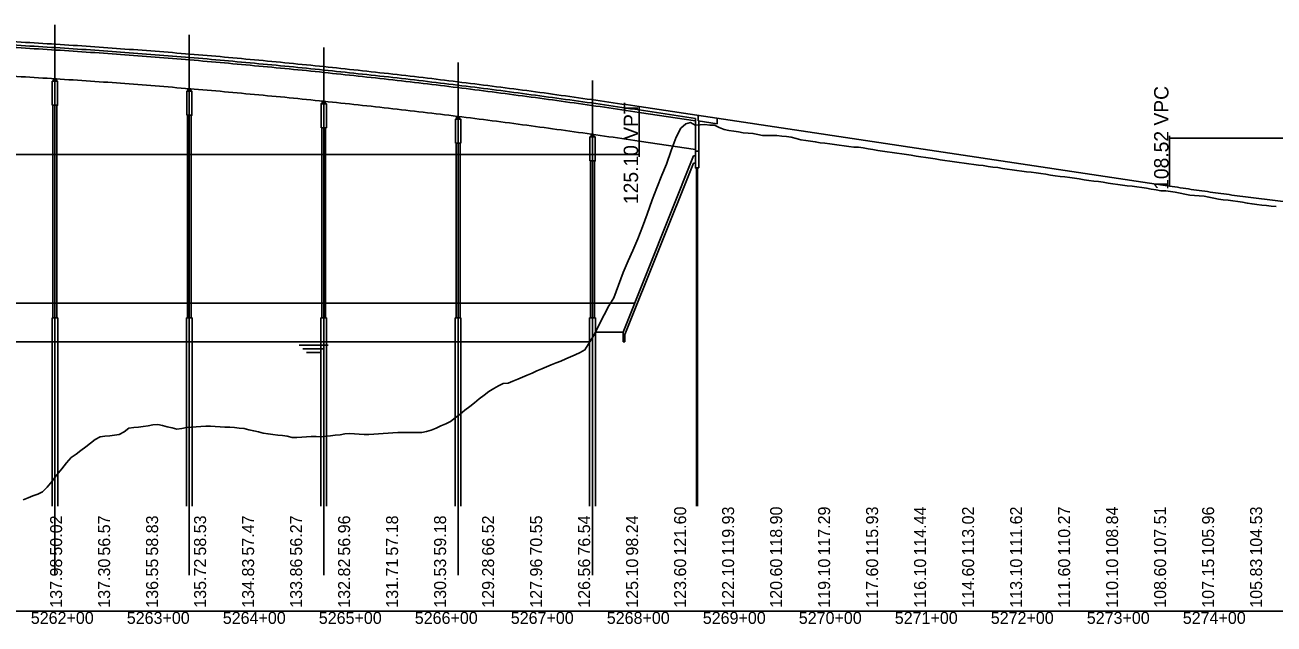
# Model space of a CAD drawing. Extents: x 2121671 to 2169879, y 557274 to 599957.
# Drawn here: x 2155728 to 2157029, y 579173 to 579797 of the extents above; entities that cross this region are included whole.
import ezdxf

# ---------------------------------------------------------------- set-up
doc = ezdxf.new("R2010")
doc.units = 0
for name, color, linetype in [('BR_CENTER LINES', 7, 'Continuous'), ('BR_CONCRETE', 7, 'Continuous'), ('BR_DETAILS', 7, 'Continuous'), ('BR_PRESTRESSED BEAM', 7, 'Continuous'), ('BR_STRUCTURAL STEEL', 7, 'Continuous'), ('RD_DDB_Profile_Elev', 7, 'Continuous'), ('RD_DDB_Profile_EX', 7, 'Continuous'), ('RD_DDB_Profile_PR', 7, 'Continuous'), ('RD_DDB_StaTX', 7, 'Continuous'), ('RD_DDB_StripGrade', 7, 'Continuous'), ('RD_DDB_VCLbl', 7, 'Continuous'), ('RD_GPK_Profile_Cell', 7, 'Continuous')]:
    doc.layers.add(name, color=color, linetype=linetype)

msp = doc.modelspace()

# ---------------------------------------------------------------- linework, layer by layer
at = {"layer": 'BR_CENTER LINES'}
for p, q in [((2155759.4, 579224.3), (2155759.4, 579797.3)), ((2155899.4, 579224.3), (2155899.4, 579787)), ((2156039.4, 579224.3), (2156039.4, 579773.9)), ((2156179.4, 579224.3), (2156179.4, 579758.1)), ((2156319.4, 579224.3), (2156319.4, 579739.4))]:
    msp.add_line(p, q, dxfattribs=at)
at = {"layer": 'BR_CONCRETE'}
for p, q in [((2155757.4, 579713.7), (2155757.4, 579492.4)), ((2155761.4, 579713.7), (2155761.4, 579492.4)), ((2155897.4, 579703.3), (2155897.4, 579492.4)), ((2155901.4, 579703.3), (2155901.4, 579492.4)), ((2156367.9, 579708.8), (2156426.6, 579700)), ((2156429.4, 579697.3), (2156429.4, 579703.1)), ((2156037.4, 579690.2), (2156037.4, 579492.4)), ((2156041.4, 579690.2), (2156041.4, 579492.4)), ((2156426.6, 579665.9), (2156426.6, 579700)), ((2156429.4, 579697.3), (2156449.4, 579694.3)), ((2156430.1, 579665.9), (2156430.1, 579697.2)), ((2156449.4, 579694.3), (2156449.4, 579700.1)), ((2156177.4, 579674.3), (2156177.4, 579492.4)), ((2156181.4, 579674.3), (2156181.4, 579492.4)), ((2156317.4, 579655.7), (2156317.4, 579492.4)), ((2156321.4, 579655.7), (2156321.4, 579492.4)), ((2155756.4, 579492.4), (2155756.4, 579296.1)), ((2155756.4, 579492.4), (2155762.4, 579492.4)), ((2155762.4, 579492.4), (2155762.4, 579296.1)), ((2155896.4, 579492.4), (2155896.4, 579296.1)), ((2155896.4, 579492.4), (2155902.4, 579492.4)), ((2155902.4, 579492.4), (2155902.4, 579296.1)), ((2156036.4, 579492.4), (2156036.4, 579296.1)), ((2156036.4, 579492.4), (2156042.4, 579492.4)), ((2156042.4, 579492.4), (2156042.4, 579296.1)), ((2156176.4, 579492.4), (2156176.4, 579296.1)), ((2156176.4, 579492.4), (2156182.4, 579492.4)), ((2156182.4, 579492.4), (2156182.4, 579296.1)), ((2156316.4, 579492.4), (2156316.4, 579296.1)), ((2156316.4, 579492.4), (2156322.4, 579492.4)), ((2156322.4, 579492.4), (2156322.4, 579296.1))]:
    msp.add_line(p, q, dxfattribs=at)
for points in [[(2155756.7, 579713.7), (2155762.2, 579713.7), (2155762.2, 579738.7), (2155756.7, 579738.7)], [(2155896.7, 579703.3), (2155902.2, 579703.3), (2155902.2, 579728.3), (2155896.7, 579728.3)], [(2156036.7, 579690.2), (2156042.2, 579690.2), (2156042.2, 579715.2), (2156036.7, 579715.2)], [(2156176.7, 579674.3), (2156182.2, 579674.3), (2156182.2, 579699.3), (2156176.7, 579699.3)], [(2156316.7, 579655.7), (2156322.2, 579655.7), (2156322.2, 579680.7), (2156316.7, 579680.7)], [(2156430.1, 579648.4), (2156426.6, 579648.4), (2156426.6, 579665.9), (2156430.1, 579665.9)]]:
    msp.add_lwpolyline(points, close=True, dxfattribs=at)
msp.add_spline([(2154567.9, 579748.7), (2154603.9, 579752.4), (2154639.9, 579755.9), (2154675.9, 579759.3), (2154711.9, 579762.4), (2154747.9, 579765.4), (2154783.9, 579768.2), (2154819.9, 579770.8), (2154855.9, 579773.2), (2154891.9, 579775.5), (2154927.9, 579777.5), (2154963.9, 579779.4), (2154999.9, 579781.1), (2155035.9, 579782.6), (2155071.9, 579783.9), (2155107.9, 579785), (2155143.9, 579786), (2155179.9, 579786.8), (2155215.9, 579787.3), (2155251.9, 579787.7), (2155287.9, 579787.9), (2155323.9, 579788), (2155359.9, 579787.8), (2155395.9, 579787.5), (2155431.9, 579787), (2155467.9, 579786.3), (2155503.9, 579785.4), (2155539.9, 579784.3), (2155575.9, 579783), (2155611.9, 579781.6), (2155647.9, 579780), (2155683.9, 579778.2), (2155719.9, 579776.2), (2155755.9, 579774), (2155791.9, 579771.6), (2155827.9, 579769.1), (2155863.9, 579766.3), (2155899.9, 579763.4), (2155935.9, 579760.3), (2155971.9, 579757), (2156007.9, 579753.6), (2156043.9, 579749.9), (2156079.9, 579746.1), (2156115.9, 579742.1), (2156151.9, 579737.9), (2156187.9, 579733.5), (2156223.9, 579728.9), (2156259.9, 579724.1), (2156295.9, 579719.2), (2156331.9, 579714.1), (2156367.9, 579708.8)], degree=3, dxfattribs=at)
at = {"layer": 'BR_DETAILS'}
for p, q in [((2156351.2, 579477.4), (2156424.6, 579660.9)), ((2156353.2, 579474.9), (2156424.6, 579653.4)), ((2156426.6, 579660.9), (2156424.6, 579660.9)), ((2156426.6, 579653.4), (2156424.6, 579653.4)), ((2156351.2, 579477.4), (2156322.5, 579477.4)), ((2156351.2, 579477.4), (2156351.2, 579467.4)), ((2156351.2, 579467.4), (2156353.2, 579467.4)), ((2156353.2, 579467.4), (2156353.2, 579474.9))]:
    msp.add_line(p, q, dxfattribs=at)
for points in [[(2155757.9, 579741.2), (2155758.9, 579741.2), (2155758.9, 579738.7), (2155757.9, 579738.7)], [(2155759.9, 579741.2), (2155760.9, 579741.2), (2155760.9, 579738.7), (2155759.9, 579738.7)], [(2155897.9, 579730.8), (2155898.9, 579730.8), (2155898.9, 579728.3), (2155897.9, 579728.3)], [(2155899.9, 579730.8), (2155900.9, 579730.8), (2155900.9, 579728.3), (2155899.9, 579728.3)], [(2156037.9, 579717.7), (2156038.9, 579717.7), (2156038.9, 579715.2), (2156037.9, 579715.2)], [(2156039.9, 579717.7), (2156040.9, 579717.7), (2156040.9, 579715.2), (2156039.9, 579715.2)], [(2156177.9, 579701.8), (2156178.9, 579701.8), (2156178.9, 579699.3), (2156177.9, 579699.3)], [(2156179.9, 579701.8), (2156180.9, 579701.8), (2156180.9, 579699.3), (2156179.9, 579699.3)], [(2156317.9, 579683.2), (2156318.9, 579683.2), (2156318.9, 579680.7), (2156317.9, 579680.7)], [(2156319.9, 579683.2), (2156320.9, 579683.2), (2156320.9, 579680.7), (2156319.9, 579680.7)]]:
    msp.add_lwpolyline(points, close=True, dxfattribs=at)
at = {"layer": 'BR_PRESTRESSED BEAM'}
for p, q in [((2156367.9, 579706.3), (2156426.6, 579697.5)), ((2156367.9, 579676.3), (2156426.6, 579667.5))]:
    msp.add_line(p, q, dxfattribs=at)
for points in [[(2154567.9, 579746.2), (2154603.9, 579749.9), (2154639.9, 579753.4), (2154675.9, 579756.8), (2154711.9, 579759.9), (2154747.9, 579762.9), (2154783.9, 579765.7), (2154819.9, 579768.3), (2154855.9, 579770.7), (2154891.9, 579773), (2154927.9, 579775), (2154963.9, 579776.9), (2154999.9, 579778.6), (2155035.9, 579780.1), (2155071.9, 579781.4), (2155107.9, 579782.5), (2155143.9, 579783.5), (2155179.9, 579784.3), (2155215.9, 579784.8), (2155251.9, 579785.2), (2155287.9, 579785.4), (2155323.9, 579785.5), (2155359.9, 579785.3), (2155395.9, 579785), (2155431.9, 579784.5), (2155467.9, 579783.8), (2155503.9, 579782.9), (2155539.9, 579781.8), (2155575.9, 579780.5), (2155611.9, 579779.1), (2155647.9, 579777.5), (2155683.9, 579775.7), (2155719.9, 579773.7), (2155755.9, 579771.5), (2155791.9, 579769.1), (2155827.9, 579766.6), (2155863.9, 579763.8), (2155899.9, 579760.9), (2155935.9, 579757.8), (2155971.9, 579754.5), (2156007.9, 579751.1), (2156043.9, 579747.4), (2156079.9, 579743.6), (2156115.9, 579739.6), (2156151.9, 579735.4), (2156187.9, 579731), (2156223.9, 579726.4), (2156259.9, 579721.6), (2156295.9, 579716.7), (2156331.9, 579711.6), (2156367.9, 579706.3)], [(2154567.9, 579716.2), (2154603.9, 579719.9), (2154639.9, 579723.4), (2154675.9, 579726.8), (2154711.9, 579729.9), (2154747.9, 579732.9), (2154783.9, 579735.7), (2154819.9, 579738.3), (2154855.9, 579740.7), (2154891.9, 579743), (2154927.9, 579745), (2154963.9, 579746.9), (2154999.9, 579748.6), (2155035.9, 579750.1), (2155071.9, 579751.4), (2155107.9, 579752.5), (2155143.9, 579753.5), (2155179.9, 579754.3), (2155215.9, 579754.8), (2155251.9, 579755.2), (2155287.9, 579755.4), (2155323.9, 579755.5), (2155359.9, 579755.3), (2155395.9, 579755), (2155431.9, 579754.5), (2155467.9, 579753.8), (2155503.9, 579752.9), (2155539.9, 579751.8), (2155575.9, 579750.5), (2155611.9, 579749.1), (2155647.9, 579747.5), (2155683.9, 579745.7), (2155719.9, 579743.7), (2155755.9, 579741.5), (2155791.9, 579739.1), (2155827.9, 579736.6), (2155863.9, 579733.8), (2155899.9, 579730.9), (2155935.9, 579727.8), (2155971.9, 579724.5), (2156007.9, 579721.1), (2156043.9, 579717.4), (2156079.9, 579713.6), (2156115.9, 579709.6), (2156151.9, 579705.4), (2156187.9, 579701), (2156223.9, 579696.4), (2156259.9, 579691.6), (2156295.9, 579686.7), (2156331.9, 579681.6), (2156367.9, 579676.3)]]:
    msp.add_spline(points, degree=3, dxfattribs=at)
at = {"layer": 'BR_STRUCTURAL STEEL'}
for p, q in [((2156427.8, 579648.4), (2156427.8, 579296.1)), ((2156428.9, 579648.4), (2156428.9, 579296.1))]:
    msp.add_line(p, q, dxfattribs=at)
at = {"layer": 'RD_DDB_Profile_Elev'}
for p, q in [((2155599.4, 579507.4), (2156363.2, 579507.4)), ((2151953.5, 579467.4), (2156316.6, 579467.4)), ((2156013.9, 579463.7), (2156043.9, 579463.7)), ((2156017.6, 579459.9), (2156040.1, 579459.9)), ((2156021.4, 579456.2), (2156036.4, 579456.2))]:
    msp.add_line(p, q, dxfattribs=at)
at = {"layer": 'RD_DDB_Profile_EX'}
for points in [[(2156221.5, 579421.5), (2156226.5, 579423.7), (2156231.5, 579424.3), (2156236.5, 579426.4), (2156241.5, 579428.5), (2156246.5, 579430.6), (2156251.5, 579432.7), (2156256.5, 579434.8), (2156261.5, 579436.9), (2156266.5, 579439), (2156271.5, 579441.1), (2156276.5, 579443.2), (2156281.5, 579445.3), (2156286.5, 579447.3), (2156291.5, 579449.4), (2156296.5, 579451.5), (2156301.5, 579453.6), (2156306.5, 579456.2), (2156311.5, 579458.9), (2156316.5, 579467.2), (2156321.5, 579475.4), (2156326.5, 579485.2), (2156331.5, 579495.3), (2156336.5, 579504.6), (2156341.5, 579513), (2156346.5, 579526.4), (2156351.5, 579539.5), (2156356.5, 579551.5), (2156361.5, 579562.5), (2156366.5, 579574.4), (2156371.5, 579586.9), (2156376.5, 579600.3), (2156381.5, 579615.2), (2156386.5, 579627.7), (2156391.5, 579640.7), (2156396.5, 579652.2), (2156401.5, 579666.6), (2156406.5, 579680.3), (2156411.5, 579689.7), (2156416.5, 579694.5), (2156421.5, 579695.6), (2156426.5, 579692.9), (2156431.5, 579693.4), (2156436.5, 579693.6), (2156441.5, 579693.1), (2156446.5, 579693), (2156451.5, 579690.5), (2156456.5, 579688.3), (2156461.5, 579687.4), (2156466.5, 579686.7), (2156471.5, 579685.9), (2156476.5, 579685), (2156481.5, 579684.7), (2156486.5, 579684.3), (2156491.5, 579683.4), (2156496.5, 579682.1), (2156501.5, 579682.1), (2156506.5, 579682.2), (2156511.5, 579682.1), (2156516.5, 579681.4), (2156521.5, 579681.1), (2156526.5, 579680.4), (2156531.5, 579678.9), (2156536.5, 579677.8), (2156541.5, 579677.1), (2156546.5, 579676.4), (2156551.5, 579675.7), (2156556.5, 579674.6), (2156561.5, 579674.2), (2156566.5, 579673.5), (2156571.5, 579672.8), (2156576.5, 579672.2), (2156581.5, 579671.5), (2156586.5, 579670.6), (2156591.5, 579670), (2156596.5, 579670), (2156601.5, 579669.2), (2156606.5, 579668.4), (2156611.5, 579667.5), (2156616.5, 579666.7), (2156621.5, 579665.9), (2156626.5, 579665.2), (2156631.5, 579664.4), (2156636.5, 579663.7), (2156641.5, 579663), (2156646.5, 579662.3), (2156651.5, 579661.6), (2156656.5, 579660.8), (2156661.5, 579660), (2156666.5, 579659.3), (2156671.5, 579658.5), (2156676.5, 579657.8), (2156681.5, 579657), (2156686.5, 579656.3), (2156691.5, 579655.5), (2156696.5, 579654.8), (2156701.5, 579654.1), (2156706.5, 579653.4), (2156711.5, 579652.8), (2156716.5, 579652.1), (2156721.5, 579651.4)], [(2156721.5, 579651.4), (2156726.5, 579650.8), (2156731.5, 579650), (2156736.5, 579649.3), (2156741.5, 579648.7), (2156746.5, 579647.9), (2156751.5, 579647.2), (2156756.5, 579646.4), (2156761.5, 579645.7), (2156766.5, 579645.2), (2156771.5, 579644.3), (2156776.5, 579644), (2156781.5, 579643.3), (2156786.5, 579642.6), (2156791.5, 579641.8), (2156796.5, 579641), (2156801.5, 579640.2), (2156806.5, 579639.5), (2156811.5, 579639), (2156816.5, 579638.4), (2156821.5, 579637.7), (2156826.5, 579636.9), (2156831.5, 579636.1), (2156836.5, 579635.2), (2156841.5, 579634.6), (2156846.5, 579634.3), (2156851.5, 579633.5), (2156856.5, 579632.7), (2156861.5, 579631.9), (2156866.5, 579631.2), (2156871.5, 579630.5), (2156876.5, 579629.9), (2156881.5, 579629.4), (2156886.5, 579628.8), (2156891.5, 579628), (2156896.5, 579627.2), (2156901.5, 579626.4), (2156906.5, 579625.6), (2156911.5, 579624.7), (2156916.5, 579624.6), (2156921.5, 579623.8), (2156926.5, 579623), (2156931.5, 579622), (2156936.5, 579621), (2156941.5, 579620.2), (2156946.5, 579619.7), (2156951.5, 579619.3), (2156956.5, 579618.9), (2156961.5, 579618), (2156966.5, 579617), (2156971.5, 579615.9), (2156976.5, 579615.1), (2156981.5, 579614.9), (2156986.5, 579614.1), (2156991.5, 579613.4), (2156996.5, 579612.6), (2157001.5, 579611.8), (2157006.5, 579610.9), (2157011.5, 579610.3), (2157016.5, 579609.6), (2157021.5, 579609.2), (2157026.5, 579608.7), (2157031.5, 579608.1)], [(2155726.5, 579302.8), (2155731.5, 579304.7), (2155736.5, 579306.7), (2155741.5, 579308.7), (2155746.5, 579310.9), (2155751.5, 579315.9), (2155756.5, 579322.3), (2155761.5, 579328.7), (2155766.5, 579335.1), (2155771.5, 579341.4), (2155776.5, 579346.7), (2155781.5, 579350.3), (2155786.5, 579354.1), (2155791.5, 579357.9), (2155796.5, 579361.7), (2155801.5, 579365.5), (2155806.5, 579368.3), (2155811.5, 579368.9), (2155816.5, 579369.5), (2155821.5, 579370.1), (2155826.5, 579370.7), (2155831.5, 579373.4), (2155836.5, 579377.3), (2155841.5, 579377.9), (2155846.5, 579378.5), (2155851.5, 579379.1), (2155856.5, 579379.7), (2155861.5, 579380.8), (2155866.5, 579381.3), (2155871.5, 579380.1), (2155876.5, 579378.8), (2155881.5, 579377.6), (2155886.5, 579376.3), (2155891.5, 579376.9), (2155896.5, 579377.9), (2155901.5, 579378.3), (2155906.5, 579378.7), (2155911.5, 579379.1), (2155916.5, 579379.5), (2155921.5, 579379.3), (2155926.5, 579379), (2155931.5, 579378.8), (2155936.5, 579378.5), (2155941.5, 579378.3), (2155946.5, 579378), (2155951.5, 579377.2), (2155956.5, 579376.9), (2155961.5, 579375.7), (2155966.5, 579374.5), (2155971.5, 579373.4), (2155976.5, 579372.2), (2155981.5, 579371.3), (2155986.5, 579370.8), (2155991.5, 579370.2), (2155996.5, 579369.7), (2156001.5, 579369.1), (2156006.5, 579367.8), (2156011.5, 579367.8), (2156016.5, 579368.1), (2156021.5, 579368.4), (2156026.5, 579368.8), (2156031.5, 579368.7), (2156036.5, 579368.3), (2156041.5, 579368.9), (2156046.5, 579369.4), (2156051.5, 579369.9), (2156056.5, 579370.4), (2156061.5, 579371.6), (2156066.5, 579371.7), (2156071.5, 579371.4), (2156076.5, 579371.2), (2156081.5, 579370.9), (2156086.5, 579370.8), (2156091.5, 579371), (2156096.5, 579371.4), (2156101.5, 579371.8), (2156106.5, 579372.2), (2156111.5, 579372.6), (2156116.5, 579372.7), (2156121.5, 579372.7), (2156126.5, 579372.7), (2156131.5, 579372.8), (2156136.5, 579372.8), (2156141.5, 579372.9), (2156146.5, 579373.8), (2156151.5, 579375.2), (2156156.5, 579377.5), (2156161.5, 579379.8), (2156166.5, 579382), (2156171.5, 579384.4), (2156176.5, 579388), (2156181.5, 579392), (2156186.5, 579396), (2156191.5, 579400), (2156196.5, 579403.9), (2156201.5, 579407.8), (2156206.5, 579411.7), (2156211.5, 579415.5), (2156216.5, 579418.6), (2156221.5, 579421.5)]]:
    msp.add_lwpolyline(points, dxfattribs=at)
at = {"layer": 'RD_DDB_Profile_PR'}
msp.add_line((2156367.9, 579712.3), (2156920.4, 579629.4), dxfattribs=at)
for points in [[(2154567.9, 579752.2), (2154603.9, 579756), (2154639.9, 579759.5), (2154675.9, 579762.8), (2154711.9, 579766), (2154747.9, 579769), (2154783.9, 579771.8), (2154819.9, 579774.4), (2154855.9, 579776.8), (2154891.9, 579779), (2154927.9, 579781.1), (2154963.9, 579782.9), (2154999.9, 579784.6), (2155035.9, 579786.1), (2155071.9, 579787.4), (2155107.9, 579788.6), (2155143.9, 579789.5), (2155179.9, 579790.3), (2155215.9, 579790.9), (2155251.9, 579791.3), (2155287.9, 579791.5), (2155323.9, 579791.5), (2155359.9, 579791.4), (2155395.9, 579791), (2155431.9, 579790.5), (2155467.9, 579789.8), (2155503.9, 579788.9), (2155539.9, 579787.8), (2155575.9, 579786.6), (2155611.9, 579785.1), (2155647.9, 579783.5), (2155683.9, 579781.7), (2155719.9, 579779.7), (2155755.9, 579777.5), (2155791.9, 579775.2), (2155827.9, 579772.6), (2155863.9, 579769.9), (2155899.9, 579767), (2155935.9, 579763.9), (2155971.9, 579760.6), (2156007.9, 579757.1), (2156043.9, 579753.5), (2156079.9, 579749.6), (2156115.9, 579745.6), (2156151.9, 579741.4), (2156187.9, 579737), (2156223.9, 579732.4), (2156259.9, 579727.7), (2156295.9, 579722.7), (2156331.9, 579717.6), (2156367.9, 579712.3)], [(2156920.4, 579629.4), (2156931.7, 579627.8), (2156943, 579626.1), (2156954.3, 579624.5), (2156965.6, 579622.9), (2156976.9, 579621.4), (2156988.2, 579619.8), (2156999.5, 579618.3), (2157010.8, 579616.9), (2157022.1, 579615.4), (2157033.4, 579614), (2157044.7, 579612.7), (2157056, 579611.3), (2157067.3, 579610), (2157078.6, 579608.8), (2157089.9, 579607.5), (2157101.2, 579606.3), (2157112.5, 579605.1), (2157123.8, 579604), (2157135.1, 579602.9), (2157146.4, 579601.8), (2157157.7, 579600.7), (2157169, 579599.7), (2157180.3, 579598.7), (2157191.6, 579597.7), (2157202.9, 579596.8), (2157214.2, 579595.9), (2157225.5, 579595), (2157236.8, 579594.2), (2157248.1, 579593.4), (2157259.4, 579592.6), (2157270.7, 579591.9), (2157282, 579591.2), (2157293.3, 579590.5), (2157304.6, 579589.8), (2157315.9, 579589.2), (2157327.2, 579588.6), (2157338.5, 579588.1), (2157349.8, 579587.5), (2157361.1, 579587), (2157372.4, 579586.6), (2157383.7, 579586.1), (2157395, 579585.7), (2157406.3, 579585.4), (2157417.6, 579585), (2157428.9, 579584.7), (2157440.2, 579584.4), (2157451.5, 579584.2), (2157462.8, 579584), (2157474.1, 579583.8), (2157485.4, 579583.6)]]:
    msp.add_spline(points, degree=3, dxfattribs=at)
at = {"layer": 'RD_DDB_VCLbl'}
for p, q in [((2156367.9, 579659.8), (2156367.9, 579712.3)), ((2156920.4, 579681.9), (2156920.4, 579629.4)), ((2156920.4, 579679.4), (2157485.4, 579679.4)), ((2154567.9, 579662.3), (2156367.9, 579662.3))]:
    msp.add_line(p, q, dxfattribs=at)
at = {"layer": 'RD_GPK_Profile_Cell'}
msp.add_line((2151067.9, 579186.8), (2157367.9, 579186.8), dxfattribs=at)

# ---------------------------------------------------------------- texts
at = {"layer": 'RD_DDB_StaTX'}
for s, p in [('5262+00', (2155734.3, 579173.5)), ('5263+00', (2155834.3, 579173.5)), ('5264+00', (2155934.3, 579173.5)), ('5265+00', (2156034.3, 579173.5)), ('5266+00', (2156134.3, 579173.5)), ('5267+00', (2156234.3, 579173.5)), ('5268+00', (2156334.3, 579173.5)), ('5269+00', (2156434.3, 579173.5)), ('5270+00', (2156534.3, 579173.5)), ('5271+00', (2156634.3, 579173.5)), ('5272+00', (2156734.3, 579173.5)), ('5273+00', (2156834.3, 579173.5)), ('5274+00', (2156934.3, 579173.5))]:
    msp.add_text(s, height=12.5, dxfattribs=at).set_placement(p)
at = {"layer": 'RD_DDB_StripGrade'}
for s, height, p in [('108.52 VPC', 15, (2156919.4, 579625.6)), ('125.10 VPT', 15, (2156366.9, 579610.8)), ('50.02', 12.5, (2155766.9, 579244.6)), ('56.57', 12.5, (2155816.9, 579244.6)), ('58.83', 12.5, (2155866.9, 579244.6)), ('58.53', 12.5, (2155916.9, 579244.6)), ('57.47', 12.5, (2155966.9, 579244.6)), ('56.27', 12.5, (2156016.9, 579244.6)), ('56.96', 12.5, (2156066.9, 579244.6)), ('57.18', 12.5, (2156116.9, 579244.6)), ('59.18', 12.5, (2156166.9, 579244.6)), ('66.52', 12.5, (2156216.9, 579244.6)), ('70.55', 12.5, (2156266.9, 579244.6)), ('76.54', 12.5, (2156316.9, 579244.6)), ('98.24', 12.5, (2156366.9, 579244.6)), ('121.60', 12.5, (2156416.9, 579244.6)), ('119.93', 12.5, (2156466.9, 579244.6)), ('118.90', 12.5, (2156516.9, 579244.6)), ('117.29', 12.5, (2156566.9, 579244.6)), ('115.93', 12.5, (2156616.9, 579244.6)), ('114.44', 12.5, (2156666.9, 579244.6)), ('113.02', 12.5, (2156716.9, 579244.6)), ('111.62', 12.5, (2156766.9, 579244.6)), ('110.27', 12.5, (2156816.9, 579244.6)), ('108.84', 12.5, (2156866.9, 579244.6)), ('107.51', 12.5, (2156916.9, 579244.6)), ('105.96', 12.5, (2156966.9, 579244.6)), ('104.53', 12.5, (2157016.9, 579244.6)), ('137.98', 12.5, (2155766.9, 579190.3)), ('137.30', 12.5, (2155816.9, 579190.3)), ('136.55', 12.5, (2155866.9, 579190.3)), ('135.72', 12.5, (2155916.9, 579190.3)), ('134.83', 12.5, (2155966.9, 579190.3)), ('133.86', 12.5, (2156016.9, 579190.3)), ('132.82', 12.5, (2156066.9, 579190.3)), ('131.71', 12.5, (2156116.9, 579190.3)), ('130.53', 12.5, (2156166.9, 579190.3)), ('129.28', 12.5, (2156216.9, 579190.3)), ('127.96', 12.5, (2156266.9, 579190.3)), ('126.56', 12.5, (2156316.9, 579190.3)), ('125.10', 12.5, (2156366.9, 579190.3)), ('123.60', 12.5, (2156416.9, 579190.3)), ('122.10', 12.5, (2156466.9, 579190.3)), ('120.60', 12.5, (2156516.9, 579190.3)), ('119.10', 12.5, (2156566.9, 579190.3)), ('117.60', 12.5, (2156616.9, 579190.3)), ('116.10', 12.5, (2156666.9, 579190.3)), ('114.60', 12.5, (2156716.9, 579190.3)), ('113.10', 12.5, (2156766.9, 579190.3)), ('111.60', 12.5, (2156816.9, 579190.3)), ('110.10', 12.5, (2156866.9, 579190.3)), ('108.60', 12.5, (2156916.9, 579190.3)), ('107.15', 12.5, (2156966.9, 579190.3)), ('105.83', 12.5, (2157016.9, 579190.3))]:
    msp.add_text(s, height=height, rotation=90, dxfattribs=at).set_placement(p)

doc.saveas('drawing.dxf')
